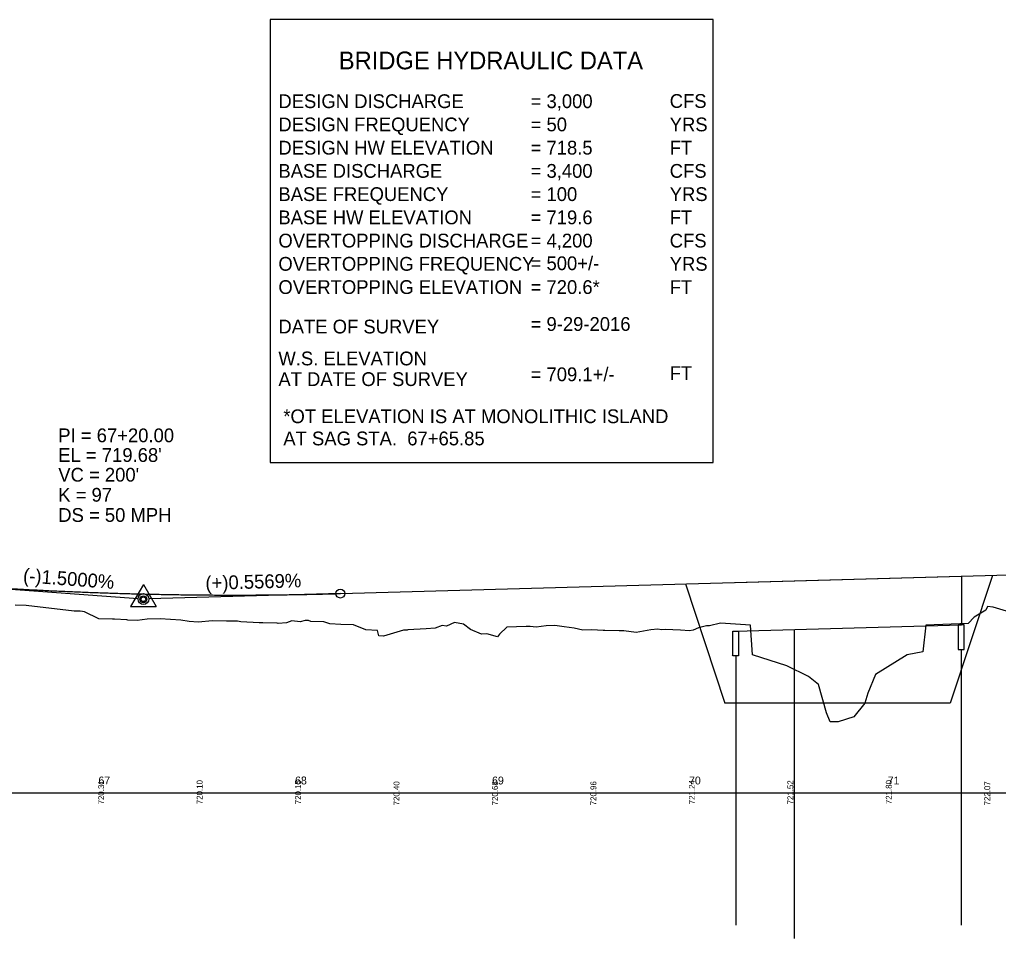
# Model space of a CAD drawing. Extents: x 1554255 to 1803987, y 659549 to 692876.
# Drawn here: x 1560450.8 to 1560947.9, y 692187.9 to 692654.6 of the extents above; entities that cross this region are included whole.
import ezdxf

# ---------------------------------------------------------------- set-up
doc = ezdxf.new("R2010")
doc.units = 0
for name, color, linetype in [('Default', 7, 'Continuous'), ('Exist Profile Cell', 7, 'Continuous'), ('Exist Vertical Profile Ground Line', 7, 'Continuous'), ('Prop Grid Mask', 7, 'Continuous'), ('Prop PFL Culvert Hydraulic Data Label CELL', 7, 'Continuous'), ('Prop PFL Text', 7, 'Continuous'), ('Prop PFL VPI Symbol CELL', 7, 'Continuous'), ('Prop Vertical Profile Curve Label', 7, 'Continuous'), ('Prop Vertical Profile Grade', 7, 'Continuous'), ('Prop Vertical Profile Grade Label', 7, 'Continuous'), ('Prop Vertical Profile Strip Grade', 7, 'Continuous'), ('Prop VPI Label', 7, 'Continuous'), ('Scratch_Level_3', 7, 'Continuous')]:
    doc.layers.add(name, color=color, linetype=linetype)

msp = doc.modelspace()

# ---------------------------------------------------------------- linework, layer by layer
at = {"layer": 'Default'}
for p, q in [((1560814.19, 692368.65), (1560929.19, 692371.85)), ((1560929.19, 692371.85), (1560929.19, 692347.19)), ((1560814.19, 692343.99), (1560929.19, 692347.19)), ((1560844.19, 692344.83), (1560844.19, 692187.93)), ((1560928.92, 692334.69), (1560928.92, 692194.63)), ((1560814.45, 692331.49), (1560814.45, 692194.63))]:
    msp.add_line(p, q, dxfattribs=at)
for points in [[(1560927.46, 692334.69), (1560930.39, 692334.69), (1560930.39, 692347.19), (1560927.46, 692347.19)], [(1560812.99, 692343.99), (1560815.92, 692343.99), (1560815.92, 692331.49), (1560812.99, 692331.49)]]:
    msp.add_lwpolyline(points, close=True, dxfattribs=at)
at = {"layer": 'Exist Profile Cell'}
msp.add_line((1554793.69, 692261.88), (1561762.5, 692261.88), dxfattribs=at)
at = {"layer": 'Exist Vertical Profile Ground Line'}
for p, q in [((1560454.07, 692357.03), (1560448.5, 692357.14)), ((1560478.55, 692354.11), (1560454.07, 692357.03)), ((1560942.27, 692356.55), (1560941.41, 692354.7)), ((1560945.27, 692356.22), (1560942.27, 692356.55)), ((1560481.51, 692354.05), (1560478.55, 692354.11)), ((1560482.76, 692354.02), (1560481.51, 692354.05)), ((1560483.77, 692353.77), (1560482.76, 692354.02)), ((1560491.07, 692350.31), (1560483.77, 692353.77)), ((1560941.41, 692354.7), (1560935.53, 692351)), ((1560953.72, 692353.54), (1560945.27, 692356.22)), ((1560498.03, 692350.05), (1560491.07, 692350.31)), ((1560498.93, 692350.07), (1560498.03, 692350.05)), ((1560505.24, 692349.78), (1560498.93, 692350.07)), ((1560505.77, 692349.49), (1560505.24, 692349.78)), ((1560510.54, 692349.32), (1560505.77, 692349.49)), ((1560515.55, 692350.07), (1560510.54, 692349.32)), ((1560522.16, 692350.22), (1560515.55, 692350.07)), ((1560532.63, 692349.54), (1560522.16, 692350.22)), ((1560536.88, 692348.8), (1560532.63, 692349.54)), ((1560541.52, 692348.59), (1560536.88, 692348.8)), ((1560548.73, 692349.19), (1560541.52, 692348.59)), ((1560555.82, 692349), (1560548.73, 692349.19)), ((1560561.37, 692349.13), (1560555.82, 692349)), ((1560563.06, 692348.63), (1560561.37, 692349.13)), ((1560572.52, 692348.14), (1560563.06, 692348.63)), ((1560574.27, 692348.26), (1560572.52, 692348.14)), ((1560581.65, 692347.98), (1560574.27, 692348.26)), ((1560582.09, 692347.9), (1560581.65, 692347.98)), ((1560586.29, 692348.18), (1560582.09, 692347.9)), ((1560589.08, 692349.24), (1560586.29, 692348.18)), ((1560593.24, 692348.72), (1560589.08, 692349.24)), ((1560595.87, 692349.31), (1560593.24, 692348.72)), ((1560597.47, 692349.4), (1560595.87, 692349.31)), ((1560598.67, 692348.91), (1560597.47, 692349.4)), ((1560605.24, 692348.73), (1560598.67, 692348.91)), ((1560608.28, 692347.77), (1560605.24, 692348.73)), ((1560613.99, 692347.42), (1560608.28, 692347.77)), ((1560620.32, 692347.19), (1560613.99, 692347.42)), ((1560626.58, 692344.61), (1560620.32, 692347.19)), ((1560665.39, 692346.8), (1560661.76, 692345.57)), ((1560667.57, 692346.46), (1560665.39, 692346.8)), ((1560671.64, 692348.3), (1560667.57, 692346.46)), ((1560676.17, 692347.47), (1560671.64, 692348.3)), ((1560679.75, 692344.77), (1560676.17, 692347.47)), ((1560718.27, 692346.65), (1560713.14, 692346.06)), ((1560722.61, 692346.88), (1560718.27, 692346.65)), ((1560727.3, 692346.17), (1560722.61, 692346.88)), ((1560799.54, 692346.66), (1560795.55, 692345.65)), ((1560801.14, 692346.69), (1560799.54, 692346.66)), ((1560806.72, 692347.95), (1560801.14, 692346.69)), ((1560821.99, 692346.93), (1560806.72, 692347.95)), ((1560932.43, 692347.8), (1560910.99, 692346.93)), ((1560935.53, 692351), (1560932.43, 692347.8)), ((1560632.46, 692344.34), (1560626.58, 692344.61)), ((1560633.2, 692341.62), (1560632.46, 692344.34)), ((1560635.63, 692341.38), (1560633.2, 692341.62)), ((1560645.81, 692344.54), (1560635.63, 692341.38)), ((1560647.59, 692344.55), (1560645.81, 692344.54)), ((1560648, 692344.56), (1560647.59, 692344.55)), ((1560657.29, 692345.21), (1560648, 692344.56)), ((1560661.76, 692345.57), (1560657.29, 692345.21)), ((1560685.41, 692342.47), (1560679.75, 692344.77)), ((1560688.14, 692342.66), (1560685.41, 692342.47)), ((1560693.48, 692341.11), (1560688.14, 692342.66)), ((1560694.44, 692342.4), (1560693.48, 692341.11)), ((1560698.17, 692345.96), (1560694.44, 692342.4)), ((1560708.02, 692346.33), (1560698.17, 692345.96)), ((1560710.13, 692346.28), (1560708.02, 692346.33)), ((1560713.14, 692346.06), (1560710.13, 692346.28)), ((1560732.45, 692345.41), (1560727.3, 692346.17)), ((1560736.83, 692344.48), (1560732.45, 692345.41)), ((1560741.3, 692344.69), (1560736.83, 692344.48)), ((1560747.1, 692344.38), (1560741.3, 692344.69)), ((1560748.07, 692344.38), (1560747.1, 692344.38)), ((1560755.21, 692344.21), (1560748.07, 692344.38)), ((1560757.71, 692344.21), (1560755.21, 692344.21)), ((1560763.9, 692343.35), (1560757.71, 692344.21)), ((1560771.3, 692344.66), (1560763.9, 692343.35)), ((1560774.94, 692344.92), (1560771.3, 692344.66)), ((1560776.72, 692344.7), (1560774.94, 692344.92)), ((1560778.56, 692344.84), (1560776.72, 692344.7)), ((1560786.4, 692344.46), (1560778.56, 692344.84)), ((1560790.92, 692344.22), (1560786.4, 692344.46)), ((1560792.89, 692344.4), (1560790.92, 692344.22)), ((1560795.55, 692345.65), (1560792.89, 692344.4))]:
    msp.add_line(p, q, dxfattribs=at)
msp.add_lwpolyline([(1560910.99, 692346.93), (1560909.49, 692333.43), (1560901.49, 692331.93), (1560885.49, 692321.93), (1560881.49, 692312.43), (1560879.99, 692307.43), (1560874.49, 692300.43), (1560866.49, 692297.93), (1560862.49, 692297.93), (1560860.49, 692302.43), (1560856.49, 692316.93), (1560851.49, 692320.93), (1560840.49, 692326.43), (1560822.99, 692331.93), (1560821.99, 692346.93)], dxfattribs=at)
at = {"layer": 'Prop Grid Mask'}
msp.add_lwpolyline([(1560578.01, 692429.56), (1560803.01, 692429.56), (1560803.01, 692654.56), (1560578.01, 692654.56)], close=True, dxfattribs=at)
at = {"layer": 'Prop PFL VPI Symbol CELL'}
for p, q in [((1560513.64, 692367.63), (1560507.19, 692356.43)), ((1560513.64, 692367.63), (1560520.14, 692356.43)), ((1560507.19, 692356.43), (1560520.14, 692356.43))]:
    msp.add_line(p, q, dxfattribs=at)
for radius in [1.75, 1.2]:
    msp.add_circle((1560513.65, 692360.15), radius, dxfattribs=at)
at = {"layer": 'Prop Vertical Profile Curve Label'}
msp.add_circle((1560613.69, 692363.06), 2.25, dxfattribs=at)
at = {"layer": 'Prop Vertical Profile Grade'}
msp.add_line((1560613.69, 692363.06), (1561003.69, 692373.92), dxfattribs=at)
msp.add_spline([(1560413.69, 692367.78), (1560417.69, 692367.48), (1560421.69, 692367.19), (1560425.69, 692366.91), (1560429.69, 692366.64), (1560433.69, 692366.38), (1560437.69, 692366.13), (1560441.69, 692365.88), (1560445.69, 692365.64), (1560449.69, 692365.41), (1560453.69, 692365.19), (1560457.69, 692364.98), (1560461.69, 692364.77), (1560465.69, 692364.57), (1560469.69, 692364.38), (1560473.69, 692364.2), (1560477.69, 692364.03), (1560481.69, 692363.87), (1560485.69, 692363.71), (1560489.69, 692363.56), (1560493.69, 692363.42), (1560497.69, 692363.29), (1560501.69, 692363.17), (1560505.69, 692363.05), (1560509.69, 692362.95), (1560513.69, 692362.85), (1560517.69, 692362.76), (1560521.69, 692362.68), (1560525.69, 692362.6), (1560529.69, 692362.54), (1560533.69, 692362.48), (1560537.69, 692362.43), (1560541.69, 692362.39), (1560545.69, 692362.36), (1560549.69, 692362.33), (1560553.69, 692362.32), (1560557.69, 692362.31), (1560561.69, 692362.31), (1560565.69, 692362.32), (1560569.69, 692362.33), (1560573.69, 692362.36), (1560577.69, 692362.39), (1560581.69, 692362.43), (1560585.69, 692362.48), (1560589.69, 692362.54), (1560593.69, 692362.61), (1560597.69, 692362.68), (1560601.69, 692362.76), (1560605.69, 692362.86), (1560609.69, 692362.95), (1560613.69, 692363.06)], degree=3, dxfattribs=at)
at = {"layer": 'Prop VPI Label'}
for p, q in [((1560413.69, 692367.78), (1560510.95, 692360.48)), ((1560613.69, 692363.06), (1560516.44, 692360.35))]:
    msp.add_line(p, q, dxfattribs=at)
msp.add_circle((1560513.69, 692360.28), 2.75, dxfattribs=at)
at = {"layer": 'Scratch_Level_3'}
for p, q in [((1560944.88, 692372.28), (1560923.41, 692307.43)), ((1560788.93, 692367.94), (1560808.96, 692307.43)), ((1560812.25, 692331.61), (1560812.25, 692331.61)), ((1560923.41, 692307.43), (1560808.96, 692307.43))]:
    msp.add_line(p, q, dxfattribs=at)

# ---------------------------------------------------------------- texts
at = {"layer": 'Default'}
for s, p in [('67', (1560490.82, 692266.13)), ('68', (1560590.68, 692266.13)), ('69', (1560690.73, 692266.13)), ('70', (1560790.76, 692266.13)), ('71', (1560891.64, 692266.13))]:
    msp.add_text(s, height=4, dxfattribs=at).set_placement(p)
at = {"layer": 'Prop PFL Culvert Hydraulic Data Label CELL'}
for s, p in [('*OT ELEVATION IS AT MONOLITHIC ISLAND', (1560584.71, 692449.6)), ('AT SAG STA.  67+65.85', (1560584.71, 692438.33))]:
    msp.add_text(s, height=6.9999, dxfattribs=at).set_placement(p)
at = {"layer": 'Prop PFL Text'}
for s, height, p in [('BRIDGE HYDRAULIC DATA', 9, (1560612.91, 692629.31)), ('DESIGN DISCHARGE', 7, (1560582.21, 692609.61)), ('= 3,000   ', 7, (1560710.29, 692609.61)), ('CFS', 7, (1560780.93, 692609.71)), ('DESIGN FREQUENCY', 7, (1560582.21, 692597.81)), ('= 50 ', 7, (1560710.29, 692597.81)), ('YRS', 7, (1560780.93, 692597.81)), ('DESIGN HW ELEVATION', 7, (1560582.21, 692586.01)), ('= 718.5   ', 7, (1560710.29, 692586.01)), ('FT', 7, (1560780.93, 692586.01)), ('BASE DISCHARGE', 7, (1560582.21, 692574.21)), ('= 3,400   ', 7, (1560710.29, 692574.21)), ('CFS', 7, (1560780.93, 692574.21)), ('BASE FREQUENCY', 7, (1560582.21, 692562.41)), ('= 100', 7, (1560710.29, 692562.41)), ('YRS', 7, (1560780.93, 692562.41)), ('BASE HW ELEVATION', 7, (1560582.21, 692550.61)), ('= 719.6   ', 7, (1560710.29, 692550.61)), ('FT', 7, (1560780.93, 692550.61)), ('OVERTOPPING DISCHARGE', 7, (1560582.21, 692538.81)), ('= 4,200   ', 7, (1560710.29, 692538.81)), ('CFS', 7, (1560780.93, 692538.81)), ('OVERTOPPING FREQUENCY', 7, (1560582.21, 692527.01)), ('= 500+/-', 7, (1560710.29, 692527.3)), ('YRS', 7, (1560780.93, 692527.01)), ('OVERTOPPING ELEVATION', 7, (1560582.21, 692515.21)), ('= 720.6*  ', 7, (1560710.29, 692515.21)), ('FT', 7, (1560780.93, 692515.21)), ('DATE OF SURVEY', 7, (1560582.21, 692495.16)), ('= 9-29-2016 ', 7, (1560710.29, 692496.46)), ('W.S. ELEVATION', 7, (1560582.21, 692478.96)), ('= 709.1+/-', 7, (1560710.29, 692470.91)), ('FT', 7, (1560780.93, 692471.51)), ('AT DATE OF SURVEY', 7, (1560582.21, 692468.46))]:
    msp.add_text(s, height=height, dxfattribs=at).set_placement(p)
at = {"layer": 'Prop Vertical Profile Curve Label'}
for s, p in [("VC = 200'", (1560470.42, 692419.91)), ('K = 97', (1560470.42, 692409.72)), ('DS = 50 MPH', (1560470.42, 692399.47))]:
    msp.add_text(s, height=7, dxfattribs=at).set_placement(p)
at = {"layer": 'Prop Vertical Profile Grade Label'}
for s, rotation, p in [('(-)1.5000%', 355.7108, (1560452.38, 692368.85)), ('(+)0.5569%', 1.5951, (1560545.25, 692364.92))]:
    msp.add_text(s, height=7, rotation=rotation, dxfattribs=at).set_placement(p)
at = {"layer": 'Prop Vertical Profile Strip Grade'}
for s, p in [('720.31', (1560493.69, 692255.97)), ('720.10', (1560543.69, 692256.09)), ('720.15', (1560593.69, 692256.05)), ('720.40', (1560643.69, 692255.48)), ('720.68', (1560693.69, 692255.49)), ('720.96', (1560743.69, 692255.52)), ('721.24', (1560793.69, 692256.04)), ('721.52', (1560843.69, 692255.96)), ('721.80', (1560893.69, 692256.09)), ('722.07', (1560943.69, 692255.45))]:
    msp.add_text(s, height=3, rotation=90, dxfattribs=at).set_placement(p)
at = {"layer": 'Prop VPI Label'}
for s, p in [('PI = 67+20.00', (1560470.42, 692439.91)), ("EL = 719.68'", (1560470.42, 692429.91))]:
    msp.add_text(s, height=7, dxfattribs=at).set_placement(p)

doc.saveas('drawing.dxf')
